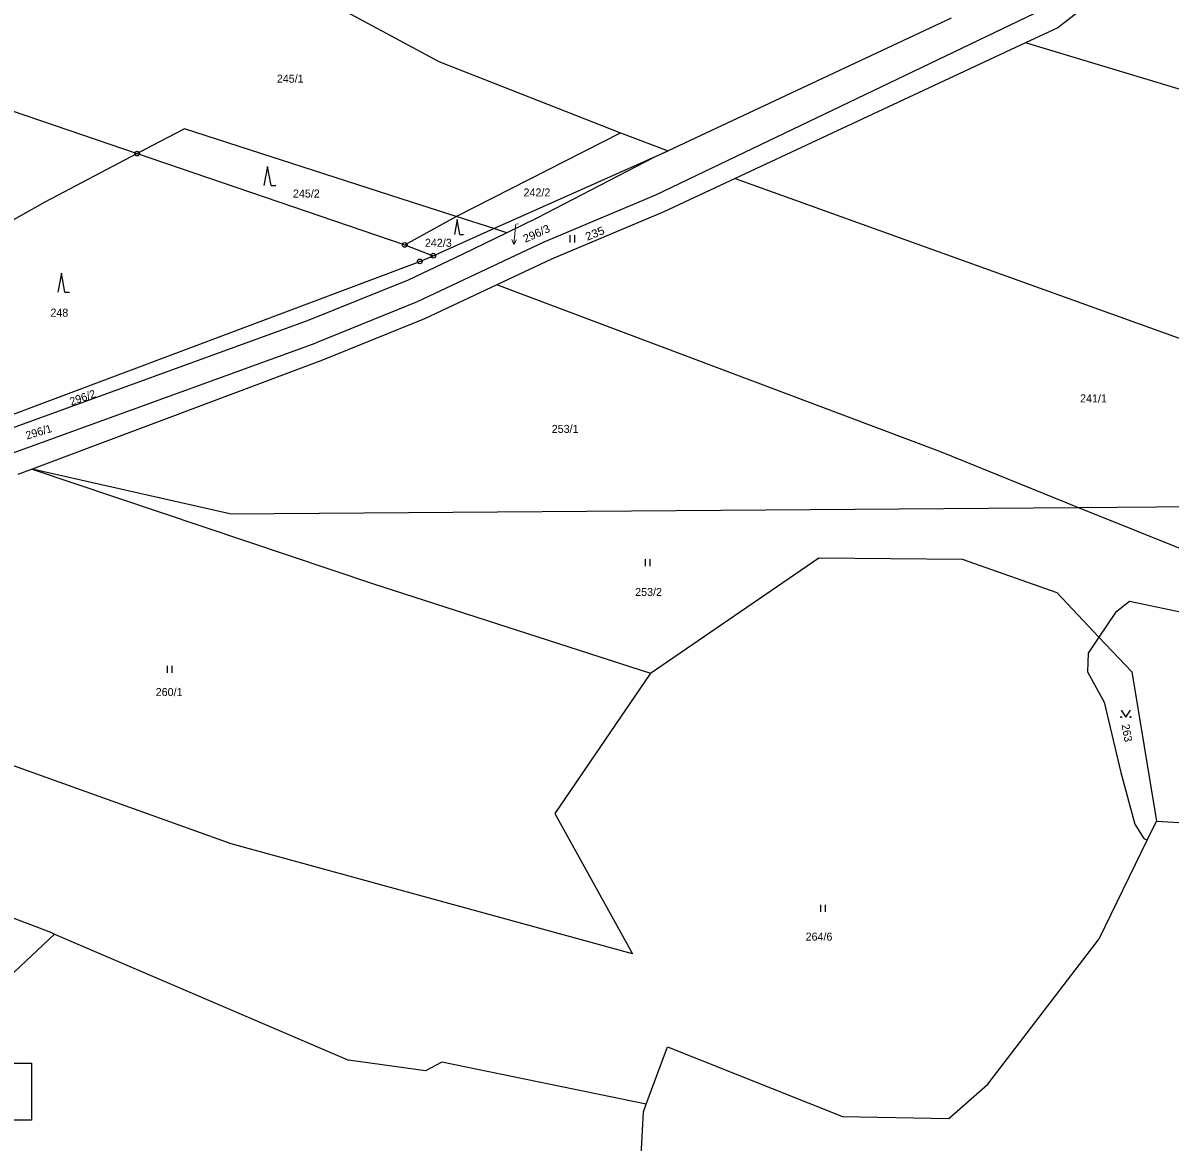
# Model space of a CAD drawing. Extents: x -645290 to -643454, y -1064771 to -1062356.
# Drawn here: x -644124.4 to -643880.7, y -1063607.4 to -1063369.7 of the extents above; entities that cross this region are included whole.
import ezdxf
from ezdxf.enums import TextEntityAlignment as Align

# ---------------------------------------------------------------- set-up
doc = ezdxf.new("R2010")
doc.units = 0
doc.header["$LTSCALE"] = 0.68
for name, color, linetype, lineweight in [('1', 7, 'Continuous', 25), ('3', 7, 'Continuous', 25), ('7', 7, 'Continuous', 13), ('8', 7, 'Continuous', 25)]:
    doc.layers.add(name, color=color, linetype=linetype, lineweight=lineweight)
doc.layers.add('2', color=7, linetype='Continuous')

msp = doc.modelspace()

# ---------------------------------------------------------------- linework, layer by layer
at = {"layer": '1'}
for p, q in [((-644060.42, -1063364.75), (-644036.09, -1063377.9)), ((-643902.76, -1063364.4), (-643990.03, -1063406.29)), ((-643899.58, -1063366.85), (-643904.6, -1063370.72)), ((-643927.27, -1063368.68), (-643987.39, -1063396.85)), ((-643904.6, -1063370.72), (-643911.48, -1063373.94)), ((-643911.48, -1063373.94), (-643973.12, -1063402.76)), ((-643765.92, -1063417.81), (-643911.48, -1063373.94)), ((-644157, -1063378.05), (-644100.19, -1063397.44)), ((-644036.09, -1063377.9), (-643997.52, -1063393.06)), ((-644090.15, -1063392.18), (-644100.19, -1063397.44)), ((-644041.86, -1063407.77), (-644090.15, -1063392.18)), ((-644032.4, -1063410.82), (-643997.52, -1063393.06)), ((-643997.52, -1063393.06), (-643987.39, -1063396.85)), ((-644024.42, -1063413.39), (-643987.39, -1063396.85)), ((-643987.39, -1063396.85), (-643990.38, -1063398.25)), ((-644100.19, -1063397.44), (-644119.82, -1063407.74)), ((-644100.19, -1063397.44), (-644043.33, -1063416.85)), ((-643990.38, -1063398.25), (-644015.25, -1063411.16)), ((-643973.12, -1063402.76), (-643988.27, -1063409.84)), ((-643973.12, -1063402.76), (-643865.15, -1063441.55)), ((-643990.03, -1063406.29), (-644013.77, -1063416.24)), ((-644119.82, -1063407.74), (-644185.68, -1063444.87)), ((-644032.4, -1063410.82), (-644041.86, -1063407.77)), ((-644043.33, -1063416.85), (-644032.4, -1063410.82)), ((-644024.42, -1063413.39), (-644032.4, -1063410.82)), ((-644015.25, -1063411.16), (-644021.67, -1063414.28)), ((-643988.27, -1063409.84), (-644012.14, -1063419.89)), ((-644037.26, -1063419.13), (-644024.42, -1063413.39)), ((-644021.67, -1063414.28), (-644024.42, -1063413.39)), ((-644013.77, -1063416.24), (-644040.7, -1063428.93)), ((-644021.67, -1063414.28), (-644031.15, -1063418.89)), ((-644043.33, -1063416.85), (-644037.26, -1063419.13)), ((-644141.12, -1063458.26), (-644040.14, -1063420.35)), ((-644031.15, -1063418.89), (-644042.58, -1063424.3)), ((-644040.14, -1063420.35), (-644037.26, -1063419.13)), ((-644012.14, -1063419.89), (-644023.77, -1063425.35)), ((-644042.58, -1063424.3), (-644064.06, -1063433)), ((-644023.77, -1063425.35), (-644039.1, -1063432.55)), ((-643929.33, -1063460.89), (-644023.77, -1063425.35)), ((-644040.7, -1063428.93), (-644062.18, -1063437.63)), ((-644064.06, -1063433), (-644145.92, -1063462.71)), ((-644039.1, -1063432.55), (-644060.8, -1063441.34)), ((-644144.15, -1063467.38), (-644062.18, -1063437.63)), ((-644060.8, -1063441.34), (-644122.49, -1063464.47)), ((-643900.36, -1063472.59), (-643929.33, -1063460.89)), ((-644122.49, -1063464.47), (-644049.97, -1063488.84)), ((-643900.36, -1063472.59), (-643772.34, -1063471.61)), ((-644080.48, -1063473.96), (-643900.36, -1063472.59)), ((-643832.05, -1063500.16), (-643900.36, -1063472.59)), ((-643991.13, -1063507.82), (-643955.39, -1063483.32)), ((-643955.39, -1063483.32), (-643924.92, -1063483.6)), ((-643924.92, -1063483.6), (-643904.8, -1063490.64)), ((-644049.97, -1063488.84), (-643991.13, -1063507.82)), ((-643904.8, -1063490.64), (-643895.86, -1063500.13)), ((-643889.39, -1063492.58), (-643892.37, -1063494.89)), ((-643877.87, -1063494.98), (-643889.39, -1063492.58)), ((-643892.37, -1063494.89), (-643895.86, -1063500.13)), ((-643895.86, -1063500.13), (-643898.12, -1063503.53)), ((-643895.86, -1063500.13), (-643888.88, -1063507.53)), ((-643898.12, -1063503.53), (-643898.28, -1063507.52)), ((-643991.13, -1063507.82), (-644011.45, -1063537.58)), ((-643898.28, -1063507.52), (-643894.73, -1063513.99)), ((-643888.88, -1063507.53), (-643883.62, -1063539.27)), ((-644080.22, -1063544.05), (-644167.24, -1063512.95)), ((-643894.73, -1063513.99), (-643891.2, -1063528.87)), ((-643891.2, -1063528.87), (-643888.22, -1063539.89)), ((-644118.31, -1063562.97), (-644186.18, -1063537.07)), ((-644011.45, -1063537.58), (-643994.94, -1063567.43)), ((-643888.22, -1063539.89), (-643886.33, -1063542.93)), ((-643885.58, -1063543.28), (-643883.62, -1063539.27)), ((-643883.62, -1063539.27), (-643857.86, -1063540.68)), ((-643886.33, -1063542.93), (-643885.58, -1063543.28)), ((-643994.94, -1063567.43), (-644080.22, -1063544.05)), ((-643895.78, -1063564.21), (-643885.58, -1063543.28)), ((-644151.77, -1063595.11), (-644117.73, -1063563.22)), ((-644118.31, -1063562.97), (-644117.73, -1063563.22)), ((-644117.73, -1063563.22), (-644055.27, -1063590)), ((-643919.44, -1063595.1), (-643895.78, -1063564.21)), ((-643992.02, -1063599.32), (-643987.49, -1063587.2)), ((-643987.49, -1063587.2), (-643950.31, -1063601.96)), ((-644038.91, -1063592.25), (-644055.27, -1063590)), ((-644035.45, -1063590.42), (-644038.91, -1063592.25)), ((-643992.02, -1063599.32), (-644035.45, -1063590.42)), ((-643927.73, -1063602.39), (-643919.44, -1063595.1)), ((-643993.61, -1063620.44), (-643992.64, -1063600.98)), ((-643992.64, -1063600.98), (-643992.02, -1063599.32)), ((-643950.31, -1063601.96), (-643927.73, -1063602.39))]:
    msp.add_line(p, q, dxfattribs=at)
msp.add_lwpolyline([(-644080.48, -1063473.96), (-644122.49, -1063464.47), (-644125.49, -1063465.59)], dxfattribs=at)
msp.add_lwpolyline([(-644122.64, -1063602.77), (-644138.8, -1063602.73), (-644138.77, -1063590.65), (-644122.61, -1063590.66)], close=True, dxfattribs=at)
at = {"layer": '3'}
for p, q in [((-644071.73, -1063404.2), (-644070.734, -1063404.2)), ((-644031.615, -1063414.6), (-644030.838, -1063414.6)), ((-644008.161, -1063416.3), (-644008.161, -1063414.8)), ((-644007.16, -1063416.3), (-644007.16, -1063414.8)), ((-644115.52, -1063426.87), (-644114.524, -1063426.87)), ((-643992.191, -1063485.08), (-643992.191, -1063483.58)), ((-643991.19, -1063485.08), (-643991.19, -1063483.58)), ((-644093.731, -1063507.74), (-644093.731, -1063506.24)), ((-644092.73, -1063507.74), (-644092.73, -1063506.24)), ((-643954.961, -1063558.51), (-643954.961, -1063557.01)), ((-643953.96, -1063558.51), (-643953.96, -1063557.01))]:
    msp.add_line(p, q, dxfattribs=at)
for points in [[(-644071.73, -1063404.2), (-644072.48, -1063400.2), (-644073.23, -1063404.2)], [(-644031.615, -1063414.6), (-644032.2, -1063411.48), (-644032.785, -1063414.6)], [(-644115.52, -1063426.87), (-644116.27, -1063422.87), (-644117.02, -1063426.87)], [(-643891.14, -1063515.639), (-643890.14, -1063517.14), (-643889.14, -1063515.639)]]:
    msp.add_lwpolyline(points, dxfattribs=at)
for centre in [(-643891.14, -1063517.1395), (-643889.14, -1063517.1395)]:
    msp.add_circle(centre, 0.1, dxfattribs=at)
at = {"layer": '7'}
msp.add_line((-644020.174, -1063416.725), (-644019.571, -1063415.781), dxfattribs=at)
msp.add_lwpolyline([(-644019.72, -1063412.43), (-644019.86, -1063413.74), (-644020.174, -1063416.725), (-644020.567, -1063415.676)], dxfattribs=at)
at = {"layer": '8'}
for centre, radius in [((-644100.19, -1063397.4399), 0.5), ((-644100.19, -1063397.4399), 0.0303), ((-644043.33, -1063416.8499), 0.5), ((-644043.33, -1063416.8499), 0.0303), ((-644037.26, -1063419.1299), 0.5), ((-644040.14, -1063420.3499), 0.5), ((-644040.14, -1063420.3499), 0.0303), ((-644037.26, -1063419.1299), 0.0303)]:
    msp.add_circle(centre, radius, dxfattribs=at)

# ---------------------------------------------------------------- texts
at = {"layer": '2'}
for s, height, p in [('245/1', 1.7, (-644070.5, -1063382.385)), ('245/2', 1.7, (-644067.08, -1063406.785)), ('242/2', 1.7, (-644018.09, -1063406.554)), ('296/3', 0.2, (-644019.72, -1063412.479)), ('242/3', 1.7, (-644039.04, -1063417.245)), ('248', 1.7, (-644118.6, -1063432.094)), ('241/1', 1.7, (-643899.86, -1063450.295)), ('253/1', 1.7, (-644012.1, -1063456.775)), ('253/2', 1.7, (-643994.38, -1063491.415)), ('260/1', 1.7, (-644096.23, -1063512.665)), ('264/6', 1.7, (-643958.17, -1063564.615))]:
    msp.add_text(s, height=height, dxfattribs=at).set_placement(p)
at = {"layer": '2', "width": 1.05}
msp.add_text('296/3', height=1.7, rotation=24, dxfattribs=at).set_placement((-644012.2745, -1063413.9863), align=Align.RIGHT)
at = {"layer": '2', "width": 1.1}
msp.add_text('235', height=1.7, rotation=22, dxfattribs=at).set_placement((-644002.6289, -1063415.1983), align=Align.CENTER)
at = {"layer": '2'}
for s, rotation, p in [('296/2', 19, (-644114.171, -1063450.991)), ('296/1', 17, (-644123.565, -1063458.196)), ('263', 280, (-643891.048, -1063518.783))]:
    msp.add_text(s, height=1.7, rotation=rotation, dxfattribs=at).set_placement(p)

doc.saveas('drawing.dxf')
